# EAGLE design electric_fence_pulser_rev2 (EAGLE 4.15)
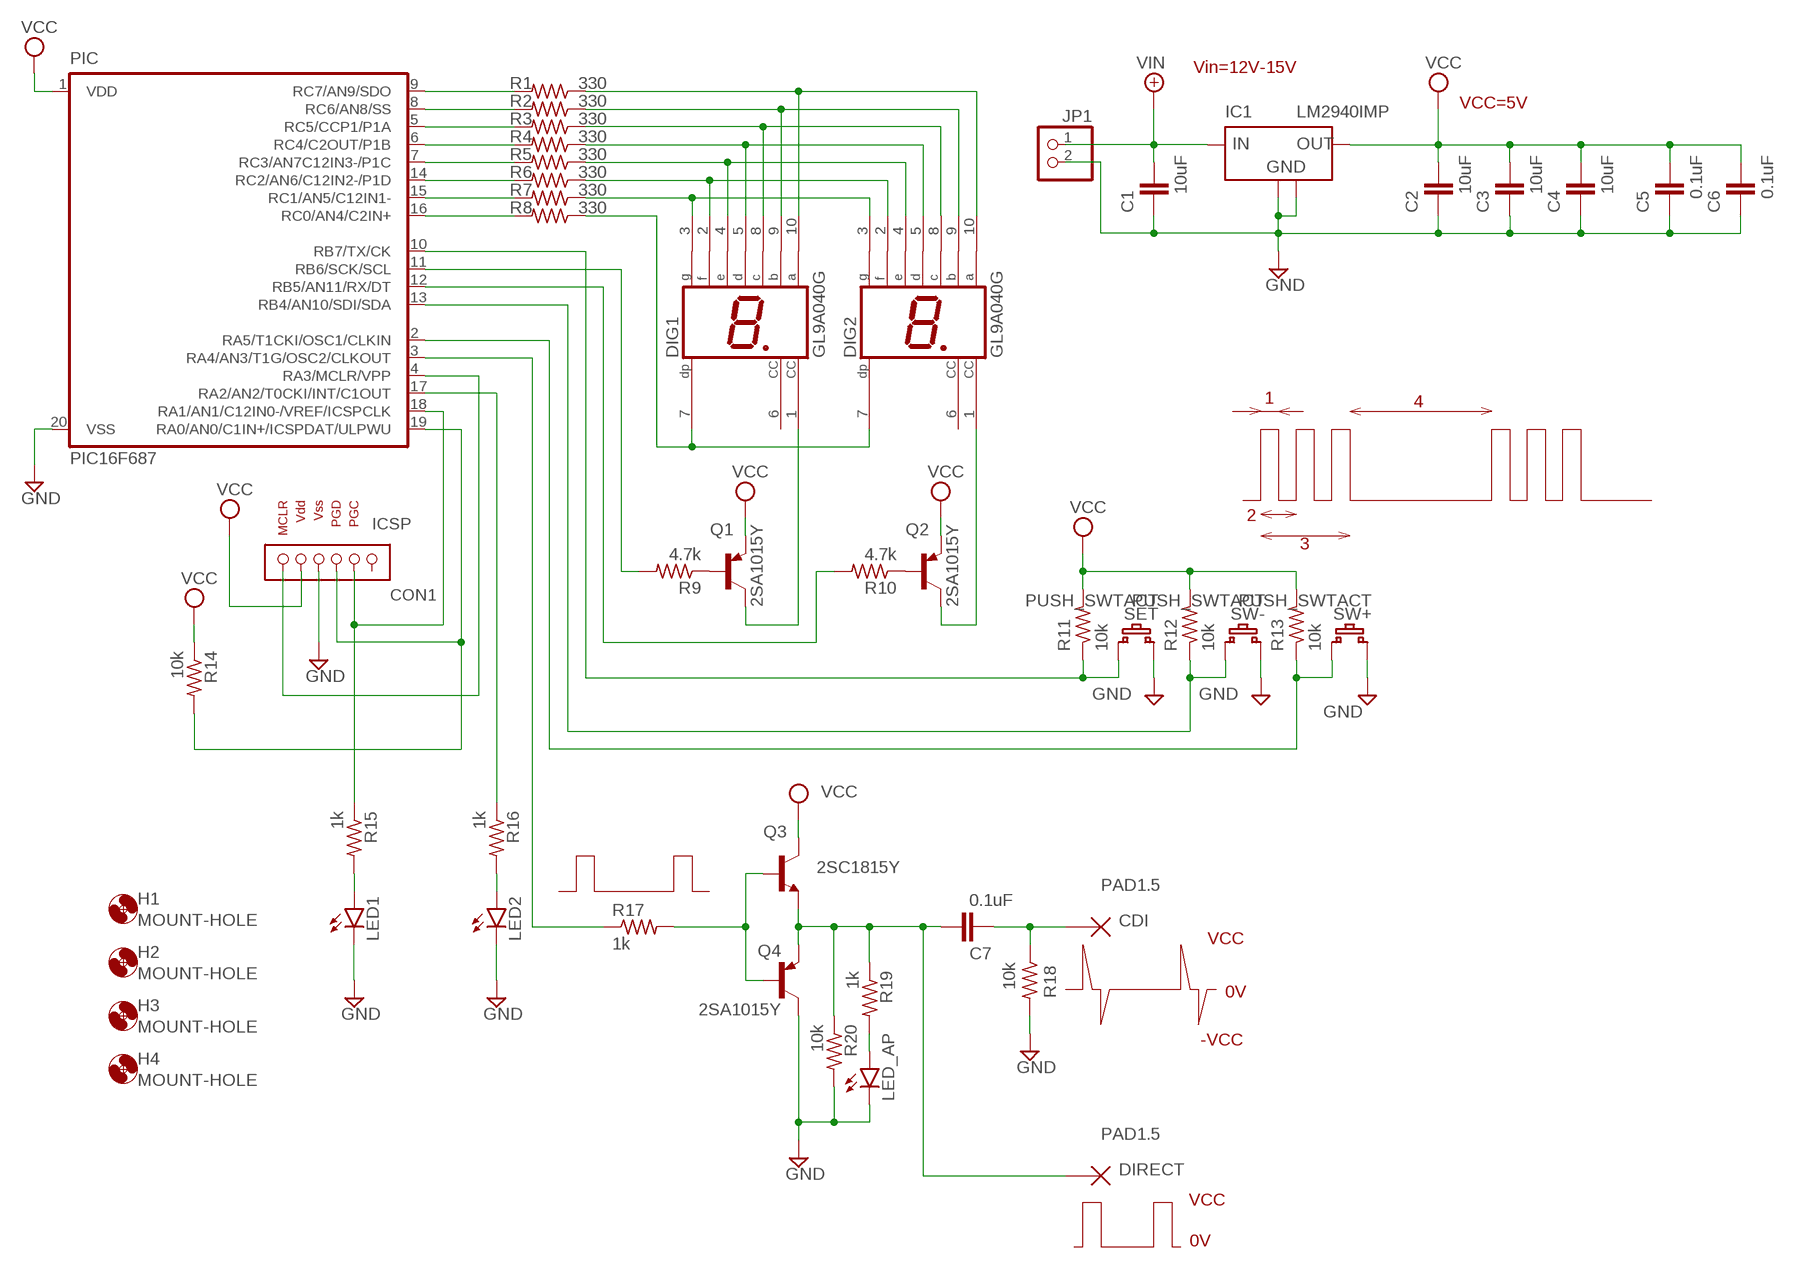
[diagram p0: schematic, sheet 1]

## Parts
C1  10uF  C-EU050-024X044_OLMX  [C050-024X044_OLMX]
C2  10uF  C-EU050-024X044_OLMX  [C050-024X044_OLMX]
C3  10uF  C-EU050-024X044_OLMX  [C050-024X044_OLMX]
C4  10uF  C-EU050-024X044_OLMX  [C050-024X044_OLMX]
C5  0.1uF  C-EU025-024X044_OLMX  [C025-024X044_OLMX]
C6  0.1uF  C-EU025-024X044_OLMX  [C025-024X044_OLMX]
C7  0.1uF  C-EU050-024X044_OLMX  [C050-024X044_OLMX]
CDI  PAD1.5  [PAD_1.5]
CON1  ICSP  PIC_ICSP  [PIC_ICSP]
DIG1  GL9A040G  HD-F103_OLMX  [HDSP-E_OLMX]
DIG2  GL9A040G  HD-F103_OLMX  [HDSP-E_OLMX]
DIRECT  PAD1.5  [PAD_1.5]
H1  MOUNT-HOLE  MOUNT-HOLEONLYRESTRICT  [3.0-HOLL-ONLY-RESTRICT]
H2  MOUNT-HOLE  MOUNT-HOLEONLYRESTRICT  [3.0-HOLL-ONLY-RESTRICT]
H3  MOUNT-HOLE  MOUNT-HOLEONLYRESTRICT  [3.0-HOLL-ONLY-RESTRICT]
H4  MOUNT-HOLE  MOUNT-HOLEONLYRESTRICT  [3.0-HOLL-ONLY-RESTRICT]
IC1  LM2940IMP  LM2940  [SOT223_OLMX]
JP1  PINHD-1X2_OLMX  [1X02_OLMX]
LED1  LED3MM_OLMX  [LED3MM_OLMX]
LED2  LED3MM_OLMX  [LED3MM_OLMX]
LED_AP  LED3MM_OLMX  [LED3MM_OLMX]
PIC  PIC16F687  PIC16F690IP_OLMX  [DIL20_OLMX]
Q1  2SA1015Y  BC636N  [TO-92-BCE?NALLOW]
Q2  2SA1015Y  BC636N  [TO-92-BCE?NALLOW]
Q3  2SC1815Y  BC635-NPN-NALLOW  [TO92-BCE_OLMX_NALLOW]
Q4  2SA1015Y  BC636N  [TO-92-BCE?NALLOW]
R1  330  R-US_0204/5_OLMX  [0204/5_OLMX]
R2  330  R-US_0204/5_OLMX  [0204/5_OLMX]
R3  330  R-US_0204/5_OLMX  [0204/5_OLMX]
R4  330  R-US_0204/5_OLMX  [0204/5_OLMX]
R5  330  R-US_0204/5_OLMX  [0204/5_OLMX]
R6  330  R-US_0204/5_OLMX  [0204/5_OLMX]
R7  330  R-US_0204/5_OLMX  [0204/5_OLMX]
R8  330  R-US_0204/5_OLMX  [0204/5_OLMX]
R9  4.7k  R-US_0204/5_OLMX  [0204/5_OLMX]
R10  4.7k  R-US_0204/5_OLMX  [0204/5_OLMX]
R11  10k  R-US_0204/5_OLMX  [0204/5_OLMX]
R12  10k  R-US_0204/5_OLMX  [0204/5_OLMX]
R13  10k  R-US_0204/5_OLMX  [0204/5_OLMX]
R14  10k  R-US_0204/5_OLMX  [0204/5_OLMX]
R15  1k  R-US_0204/5_OLMX  [0204/5_OLMX]
R16  1k  R-US_0204/5_OLMX  [0204/5_OLMX]
R17  1k  R-US_0204/5_OLMX  [0204/5_OLMX]
R18  10k  R-US_0204/5_OLMX  [0204/5_OLMX]
R19  1k  R-US_0204/5_OLMX  [0204/5_OLMX]
R20  10k  R-US_0204/5_OLMX  [0204/5_OLMX]
SET  PUSH_SWTACT  [TACT_SW]
SW+  PUSH_SWTACT  [TACT_SW]
SW-  PUSH_SWTACT  [TACT_SW]

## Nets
+12V [POWER]: C1.2 IC1.1(IN) JP1.1 ; supply symbol labelled VIN
GND [POWER]: C1.1 C2.1 C3.1 C4.1 C5.1 C6.1 CON1.VSS IC1.2(GND) IC1.4(GND) JP1.2 LED1.K(C) LED2.K(C) LED_AP.K(C) PIC.20(VSS) Q4.C R18.2 R20.2 SET.P$1_1 SW+.P$1_1 SW-.P$1_1
N$1: DIG1.7(DP) DIG2.7(DP) R8.1
N$2: PIC.9(RC7/AN9/SDO) R1.2
N$3: PIC.12(RB5/AN11/RX/DT) R10.2
N$4: PIC.15(RC1/AN5/C12IN1-) R7.2
N$5: PIC.14(RC2/AN6/C12IN2-/P1D) R6.2
N$6: PIC.7(RC3/AN7C12IN3-/P1C) R5.2
N$7: PIC.6(RC4/C2OUT/P1B) R4.2
N$8: PIC.5(RC5/CCP1/P1A) R3.2
N$9: PIC.13(RB4/AN10/SDI/SDA) R12.1 SW-.P$1_2
N$10: PIC.10(RB7/TX/CK) R11.1 SET.P$1_2
N$11: C7.1 CDI.P$1 R18.1
N$12: PIC.8(RC6/AN8/SS) R2.2
N$13: LED_AP.A R19.2
N$14: CON1.MCLR PIC.4(RA3/MCLR/VPP)
N$15: DIG1.1(CC) Q1.C
N$16: DIG2.1(CC) Q2.C
N$18: PIC.11(RB6/SCK/SCL) R9.2
N$19: LED1.A R15.2
N$20: LED2.A R16.2
N$22: Q1.B R9.1
N$23: Q2.B R10.1
N$24: PIC.17(RA2/AN2/T0CKI/INT/C1OUT) R16.1
N$25: Q3.B Q4.B R17.2
N$26: CON1.PGC PIC.18(RA1/AN1/C12IN0-/VREF/ICSPCLK) R15.1
N$27: PIC.2(RA5/T1CKI/OSC1/CLKIN) R13.1 SW+.P$1_2
N$28: PIC.3(RA4/AN3/T1G/OSC2/CLKOUT) R17.1
N$29: C7.2 DIRECT.P$1 Q3.E Q4.E R19.1 R20.1
N$31: DIG1.10(A) DIG2.10(A) R1.1
N$32: CON1.PGD PIC.19(RA0/AN0/C1IN+/ICSPDAT/ULPWU) R14.2
N$35: PIC.16(RC0/AN4/C2IN+) R8.2
N$42: DIG1.9(B) DIG2.9(B) R2.1
N$44: DIG1.5(D) DIG2.5(D) R4.1
N$45: DIG1.2(F) DIG2.2(F) R6.1
N$46: DIG1.4(E) DIG2.4(E) R5.1
N$47: DIG1.3(G) DIG2.3(G) R7.1
N$55: DIG1.8(C) DIG2.8(C) R3.1
VCC [POWER]: C2.2 C3.2 C4.2 C5.2 C6.2 CON1.VDD IC1.3(OUT) PIC.1(VDD) Q1.E Q2.E Q3.C R11.2 R12.2 R13.2 R14.1
Unconnected: CON1.NC DIG1.6(CC) DIG2.6(CC)

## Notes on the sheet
- Vin=12V-15V
- VCC=5V
- 1 | 4
- 2
- 3
- VCC
- 0V
- -VCC
- VCC
- 0V

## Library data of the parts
C1-C7 = rcl:C-EU: CAPACITOR, European symbol
CDI DIRECT = 001mylib:PAD
CON1 = 001mylib:PIC_ICSP
DIG1 DIG2 = display-hp:HD-F103: LED DISPLAY 1-character 7 segment, decimal point right
H1-H4 = holes:MOUNT-HOLE: MOUNTING HOLE with drill center marker
IC1 = linear:LM2940
JP1 = pinhead:PINHD-1X2: PIN HEADER
LED1 LED2 LED_AP = led:LED: LED
PIC = microchip-5:PIC16F690*: MICROCONTROLLER PIC16F690 18 I/O One 16-bit timer Two 8-bit timer Two comparators Precision internal oscillator-software selectable 8 MHz - 32 KHz SSP w/ I2C Compatible Address mask option EUSART LIN 2.0 Compatible ECCP+ w/ PWM Steering 12 A/D Channels ULPW Enhanced Low Power Timer 1 Timer 1 Gate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
Q1 Q2 Q4 = transistor-pnp:BC636*: PNP Transistror
Q3 = transistor:*-NPN-: NPN Transistror
R1-R20 = rcl:R-US_: RESISTOR, American symbol
SET SW+ SW- = 001mylib:PUSH_SW

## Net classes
0 default: width 0.305 mm, drill 0.305 mm
1 POWER: width 0.889 mm, drill 0.457 mm

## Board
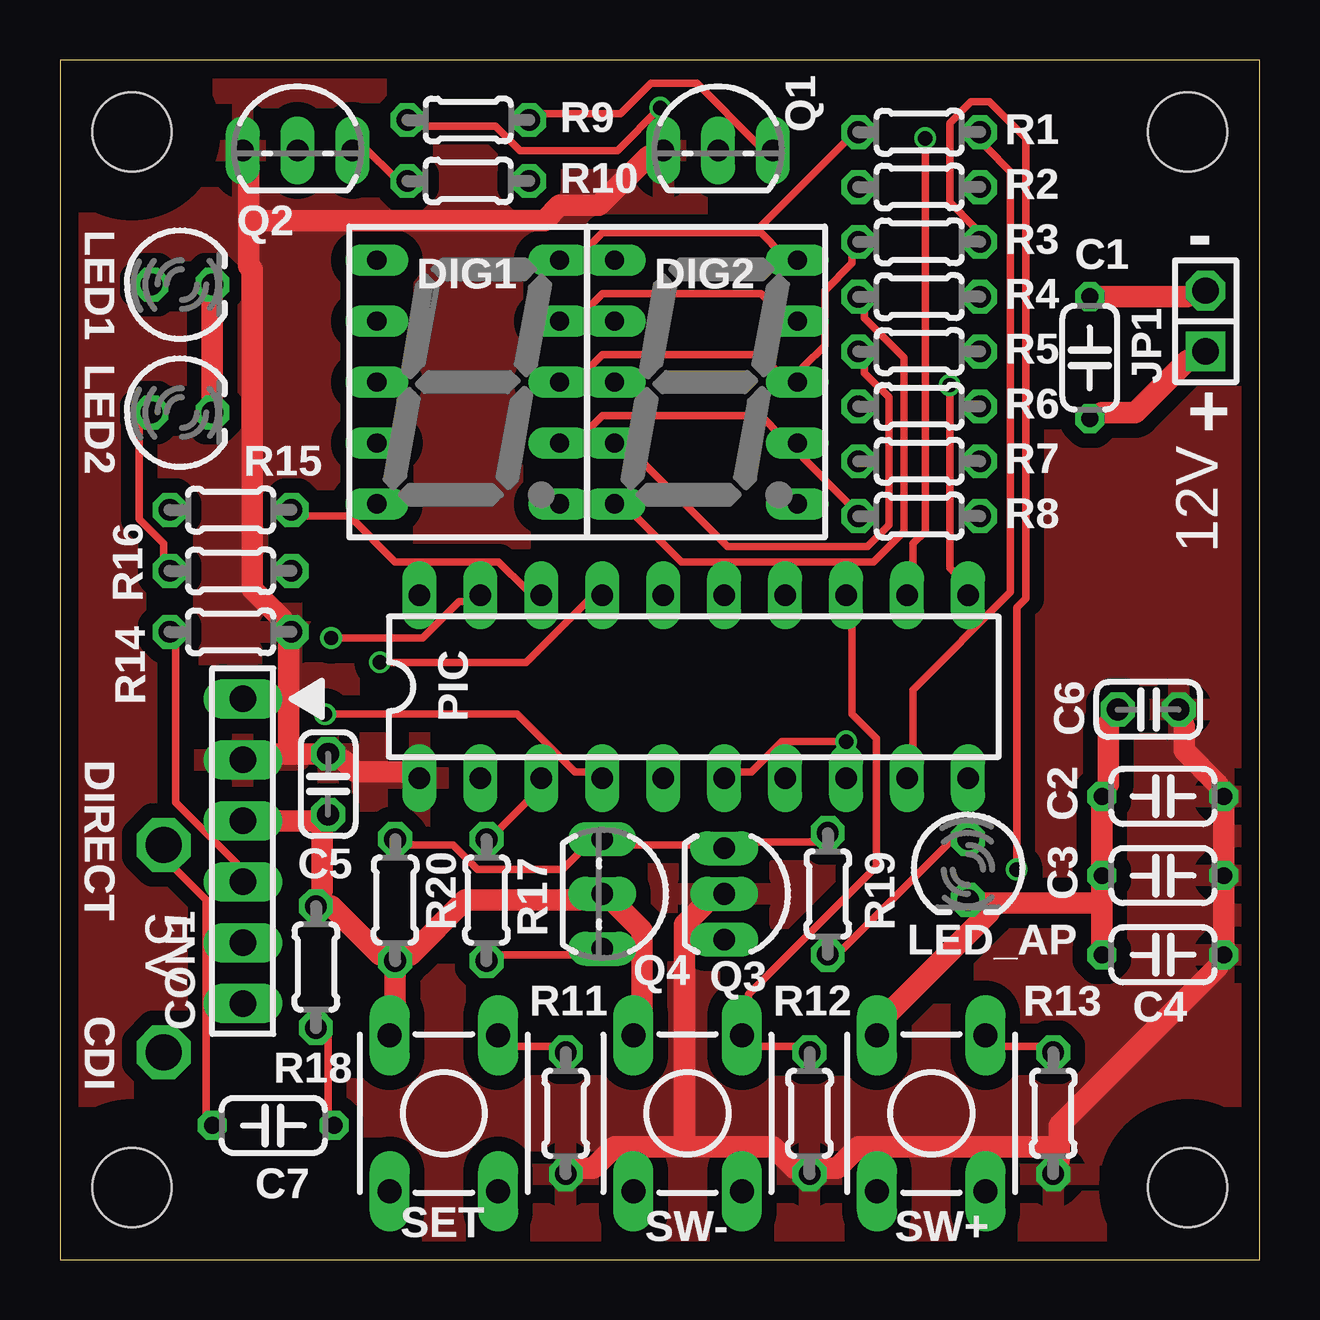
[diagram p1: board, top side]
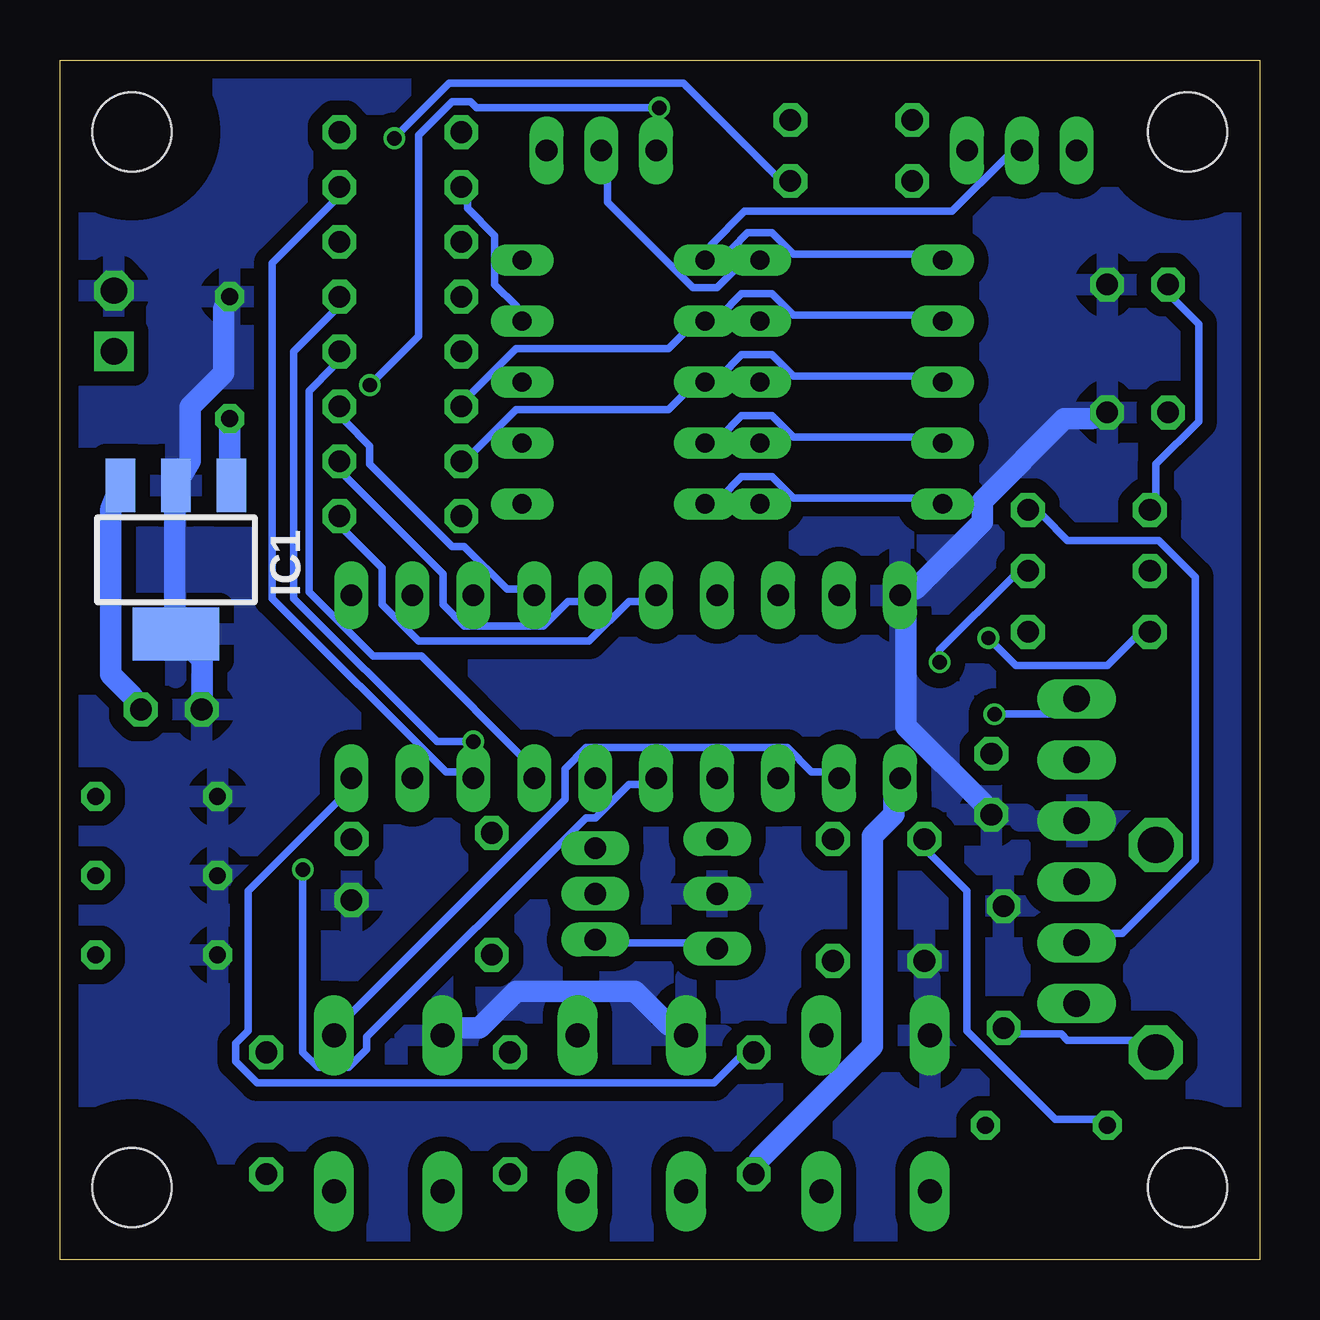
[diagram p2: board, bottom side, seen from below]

Size 50 x 50 mm. Coordinates in mm from the lower left corner, seen from the top.
Outline: 0,0 50,0 50,50 0,50 0,0
Copper layers (1*16): Top 0.035mm / dielectric 1.5mm / Bottom 0.035mm
Design rules "FUSION_IIZUKA_STANDARD": minimum track width 6mil, minimum drill 0.6mm, track to track 8mil, track to pad 8mil, pad to pad 8mil, via to via 8mil, smd to smd 0mil, copper to edge 30mil, drill to drill 10mil, minimum pad ring 10mil, minimum via ring 6mil, stop-mask expansion 2mil, vias tented up to drill 100mil, thermal gap 24mil
vRestrict: 816 lines

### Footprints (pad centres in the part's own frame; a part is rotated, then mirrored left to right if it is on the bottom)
C050-024X044_OLMX = drill 0.7 octagon: 1 -2.54,0; 2 2.54,0
C025-024X044_OLMX = drill 0.9 octagon: 1 -1.27,0; 2 1.27,0
PAD_1.5 = drill 1.5 pad 2.184 octagon: P$1 0,0
PIC_ICSP = drill 1.1 long: MCLR -6.35,0; NC 6.35,0; PGC 3.81,0; PGD 1.27,0; VDD -3.81,0; VSS -1.27,0
HDSP-E_OLMX = drill 0.8 long: 1 -3.81,5.08; 2 -3.81,2.54; 3 -3.81,0; 4 -3.81,-2.54; 5 -3.81,-5.08; 6 3.81,-5.08; 7 3.81,-2.54; 8 3.81,0; 9 3.81,2.54; 10 3.81,5.08
3.0-HOLL-ONLY-RESTRICT = hole 3.3: 0,0
SOT223_OLMX = smd 1.219 x 2.235: 1 -2.311,-3.099; 2 0,-3.099; 3 2.311,-3.099 | smd 3.6 x 2.2: 4 0,3.099
1X02_OLMX = drill 1.1 square: 1 -1.27,0 | drill 1.1 octagon: 2 1.27,0
LED3MM_OLMX = drill 0.9 octagon: A -1.27,0; K 1.27,0
DIL20_OLMX = drill 0.9 long: 1 -11.43,-3.81; 2 -8.89,-3.81; 3 -6.35,-3.81; 4 -3.81,-3.81; 5 -1.27,-3.81; 6 1.27,-3.81; 7 3.81,-3.81; 8 6.35,-3.81; 9 8.89,-3.81; 10 11.43,-3.81; 11 11.43,3.81; 12 8.89,3.81; 13 6.35,3.81; 14 3.81,3.81; 15 1.27,3.81; 16 -1.27,3.81; 17 -3.81,3.81; 18 -6.35,3.81; 19 -8.89,3.81; 20 -11.43,3.81
TO-92-BCE?NALLOW = drill 0.9 long: B 2.286,0; C 0,0; E -2.286,0
TO92-BCE_OLMX_NALLOW = drill 0.9 long: B 1.905,0; C 0,0; E -1.905,0
0204/5_OLMX = drill 0.9 octagon: 1 -2.54,0; 2 2.54,0
TACT_SW = drill 1 pad 1.676 long: P$1_1 -2.261,3.251; P$1_2 2.261,3.251; P$2_1 -2.261,-3.251; P$2_2 2.261,-3.251

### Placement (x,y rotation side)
C1  42.93,37.59 270 top
C2  45.97,19.3 0 top
C3  45.97,16 0 top
C4  45.97,12.7 0 top
C5  11.18,19.81 90 top
C6  45.36,22.93 0 top
C7  8.89,5.59 180 top
CDI  4.32,8.64 270 top
CON1  7.62,17.02 270 top
DIG1  17.02,36.58 0 top
DIG2  26.92,36.58 0 top
DIRECT  4.32,17.27 270 top
H1  47,47 0 top
H2  47,3 0 top
H3  3,3 0 top
H4  3,47 0 top
IC1  45.17,29.17 180 bottom
JP1  47.75,39.12 90 top
LED1  5.08,40.64 0 top
LED2  5.08,35.31 0 top
LED_AP  37.85,16.26 270 top
PIC  26.42,23.88 0 top
Q1  27.43,46.23 0 top
Q2  9.91,46.23 0 top
Q3  27.69,15.24 270 top
Q4  22.61,15.24 270 top
R1  35.81,46.99 0 top
R2  35.81,44.7 0 top
R3  35.81,42.42 0 top
R4  35.81,40.13 0 top
R5  35.81,37.85 0 top
R6  35.81,35.56 0 top
R7  35.81,33.27 0 top
R8  35.81,30.99 0 top
R9  17.02,47.5 180 top
R10  17.02,44.96 0 top
R11  21.08,6.1 270 top
R12  31.24,6.1 270 top
R13  41.4,6.1 270 top
R14  7.11,26.16 180 top
R15  7.11,31.24 180 top
R16  7.11,28.7 180 top
R17  17.78,14.99 270 top
R18  10.67,12.19 90 top
R19  32,15.24 270 top
R20  13.97,14.99 270 top
SET  16,6.1 0 top
SW+  36.32,6.1 0 top
SW-  26.16,6.1 0 top

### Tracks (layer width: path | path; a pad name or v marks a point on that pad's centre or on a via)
+12V
  Top 0.889: C1.2 43.43,35.31 44.83,35.31 46.99,37.47 JP1.1
  Bottom 0.889: IC1.1 42.93,33.27 C1.2
GND
  Top 0.889: 43.43,14.86 C4.1 | 43.43,14.86 C3.1 C2.1 43.69,19.81 43.69,22.35 C6.1 | 38.73,14.86 38.48,14.86 LED_AP.K | 38.73,14.86 43.43,14.86 | SW+.P$1_1 34.42,10.16 38.73,14.48 38.73,14.86 | C1.1 46.99,40.13 JP1.2 | SW-.P$1_1 24.26,10.16 24.26,13.72 23.11,14.86 Q4.C 21.97,14.99 16.89,14.99 14.61,12.7 R20.2 | LED2.K LED1.K | R20.2 13.97,10.16 SET.P$1_1 | CON1.VSS 10.54,18.29 C5.1 10.92,17.91 10.92,15.37 R18.2 11.3,14.73 13.34,12.7 R20.2
  Bottom 0.889: C6.1 44.07,23.62 44.07,25.02 IC1.4 45.21,27.05 45.21,31.24 IC1.2 44.58,33.27 44.58,35.56 43.18,36.96 43.18,39.62 C1.1 | C5.1 11.56,19.05 14.73,22.23 14.73,27.05 PIC.20 14.35,27.94 11.56,30.73 11.56,31.62 8.13,35.05 6.99,35.05 LED2.K | SW+.P$1_1 33.27,9.65 32.51,9.65 30.99,11.18 26.04,11.18 24.64,9.78 SW-.P$1_1
  pour Bottom (isolate 0.61): 0,50 50,50 50,0 0,0
N$1
  Top 0.305: DIG1.7 21.46,34.29 21.72,34.29 22.61,35.18 29.21,35.18 30.1,34.29 DIG2.7 30.99,33.4 32.89,31.5 R8.1
N$2
  Top 0.305: PIC.9 35.56,20.7 35.56,23.75 39.62,27.81 39.62,45.34 38.61,46.35 R1.2
N$3  (via drill 0.6)
  Top 0.305: v36.07,46.74 36.07,30.35 35.56,29.84 35.56,28.32 PIC.12
  Bottom 0.305: v36.07,46.74 33.78,49.02 24,49.02 20.19,45.21 R10.2
N$4
  Bottom 0.305: PIC.15 28.32,27.43 28.83,27.43 29.84,26.42 33.15,26.42 34.04,27.3 34.04,28.57 38.1,32.64 R7.2
N$5
  Bottom 0.305: PIC.14 30.86,27.94 31.37,27.94 33.15,29.72 33.66,29.72 37.08,33.15 37.08,33.91 38.1,34.92 R6.2
N$6
  Bottom 0.305: PIC.7 30.48,20.7 34.92,25.15 36.96,25.15 39.62,27.81 39.62,36.2 38.61,37.21 R5.2
N$7  (via drill 0.6)
  Top 0.305: v32.77,21.59 30.1,21.59 28.83,20.32 28.32,20.32 PIC.6
  Bottom 0.305: v32.77,21.59 34.29,21.59 40.26,27.56 40.26,37.85 38.61,39.5 R4.2
N$8  (via drill 0.6)
  Top 0.305: v39.88,16.26 39.88,27.18 40.26,27.56 40.26,46.74 38.73,48.26 37.97,48.26 37.08,47.37 37.08,44.07 38.1,43.05 R3.2
  Bottom 0.305: v39.88,16.26 39.88,8.64 39.24,8 37.97,8 37.21,8.76 37.21,9.27 28.07,18.41 27.69,18.41 26.29,19.81 25.78,19.81 PIC.5
N$9
  Top 0.305: R12.1 30.61,8.89 29.08,8.89 SW-.P$1_2 28.7,10.16 28.7,11.05 34.04,16.38 34.04,21.72 33.02,22.73 33.02,27.05 PIC.13
N$10
  Top 0.305: R11.1 20.45,8.89 18.92,8.89 SET.P$1_2
  Bottom 0.305: PIC.10 38.1,19.43 42.16,15.37 42.16,9.53 42.67,9.02 42.67,8.26 41.78,7.37 22.73,7.37 21.72,8.38 R11.1
N$11
  Top 0.305: C7.1 11.18,6.1 11.18,9.27 R18.1
  Bottom 0.305: R18.1 10.03,9.4 8.26,9.4 8,9.14 5.33,9.14 CDI.P$1
N$12
  Bottom 0.305: PIC.8 33.4,20.32 33.91,20.32 41.15,27.56 41.15,41.53 38.61,44.07 R2.2
N$13
  Top 0.305: R19.2 32.64,12.95 37.21,17.53 LED_AP.A
N$14  (via drill 0.6)
  Top 0.305: v11.05,22.73 19.05,22.73 21.46,20.32 21.97,20.32 PIC.4
  Bottom 0.305: v11.05,22.73 8.13,22.73 CON1.MCLR
N$15
  Bottom 0.305: DIG1.1 13.84,41.91 19.43,41.91 20.32,42.8 21.34,42.8 21.97,42.16 21.97,41.15 22.61,40.51 23.62,40.51 27.18,44.07 27.18,45.59 Q1.C
N$16
  Bottom 0.305: DIG2.1 22.86,42.29 21.46,43.69 12.83,43.69 10.54,45.97 Q2.C
N$18  (via drill 0.6)
  Top 0.305: v25.02,48.01 23.24,46.23 19.18,46.23 18.16,47.24 15.11,47.24 R9.2 | v37.08,36.45 37.08,28.83 37.59,28.32 PIC.11
  Bottom 0.305: v25.02,48.01 32.64,48.01 32.89,48.26 33.66,48.26 35.05,46.86 35.05,38.48 v37.08,36.45
N$19
  Bottom 0.305: R15.2 4.32,31.88 4.32,33.15 2.54,34.92 2.54,38.99 3.56,40.01 LED1.A
N$20
  Top 0.305: R16.2 4.32,29.34 4.32,29.84 3.3,30.86 3.3,34.92 LED2.A
N$22
  Top 0.305: R9.1 20.19,47.75 23.37,47.75 24.64,49.02 26.54,49.02 29.08,46.48 Q1.B
N$23
  Top 0.305: R10.1 13.84,45.21 12.83,46.23 Q2.B
N$24  (via drill 0.6)
  Top 0.305: v13.34,24.89 19.43,24.89 21.97,27.43 PIC.17
  Bottom 0.305: v13.34,24.89 13.34,25.4 10.29,28.45 R16.1
N$25
  Top 0.305: R17.2 18.41,12.7 21.97,12.7 Q4.B
  Bottom 0.305: Q3.B 27.05,13.21 23.24,13.21 Q4.B
N$26
  Top 0.305: R15.1 10.29,30.99 12.06,30.99 13.97,29.08 18.29,29.08 19.43,27.94 PIC.18
  Bottom 0.305: CON1.PGC 6.86,13.59 5.71,13.59 2.67,16.64 2.67,28.45 4.19,29.97 8,29.97 9.02,30.99 R15.1
N$27
  Top 0.305: R13.1 40.77,8.89 39.24,8.89 SW+.P$1_2
  Bottom 0.305: PIC.2 18.16,20.32 18.67,20.32 19.68,21.34 28.07,21.34 28.96,20.45 28.96,19.18 38.1,10.03 SW+.P$1_2
N$28
  Top 0.305: R17.1 18.29,17.91 19.81,19.43 PIC.3
N$29
  Top 0.305: C7.2 6.1,6.1 6.1,14.99 4.83,16.26 DIRECT.P$1 | R19.1 31.5,17.4 28.32,17.4 Q3.E 27.05,17.27 23.24,17.27 Q4.E 21.97,17.27 20.95,16.26 17.4,16.26 16.38,17.27 14.61,17.27 R20.1
  Bottom 0.305: C7.2 6.86,5.84 8.51,5.84 12.19,9.53 12.19,15.37 13.72,16.89 R20.1
N$31
  Top 0.305: 29.08,42.8 29.21,42.8 30.1,41.91 DIG2.10 | 29.08,42.8 22.61,42.8 21.72,41.91 21.46,41.91 DIG1.10 | R1.1 32.77,46.61 29.08,42.93 29.08,42.8
N$32  (via drill 0.6)
  Top 0.305: R14.2 4.83,25.53 4.83,19.05 7.37,16.51 CON1.PGD | v11.3,25.91 15.11,25.91 16.64,27.43 16.89,27.43 PIC.19
  Bottom 0.305: v11.3,25.91 10.16,24.77 6.35,24.77 5.21,25.91 R14.2
N$35
  Bottom 0.305: PIC.16 25.78,27.43 26.29,27.43 27.94,25.78 35.05,25.78 36.58,27.3 36.58,28.83 38.1,30.35 R8.2
N$42
  Top 0.305: DIG1.9 21.46,39.37 21.72,39.37 22.61,40.26 29.21,40.26 30.1,39.37 DIG2.9
  Bottom 0.305: R2.1 33.02,44.07 33.02,43.81 31.88,42.67 31.88,40.64 30.99,39.75 DIG2.9
N$44
  Top 0.305: R4.1 33.53,39.5 33.53,39.24 35.18,37.59 35.18,30.35 33.91,29.08 25.91,29.08 23.75,31.24 DIG2.5
  Bottom 0.305: DIG1.5 13.84,31.75 19.43,31.75 20.32,32.64 21.59,32.64 22.48,31.75 DIG2.5
N$45
  Bottom 0.305: DIG1.2 13.84,39.37 19.43,39.37 20.32,40.26 21.59,40.26 22.48,39.37 DIG2.2 23.75,38.86 24.64,37.97 30.99,37.97 32.89,36.07 R6.1
N$46
  Top 0.305: R5.1 33.53,37.21 33.53,36.96 34.54,35.94 34.54,30.61 33.66,29.72 27.81,29.72 23.75,33.78 DIG2.4
  Bottom 0.305: DIG1.4 13.84,34.29 19.43,34.29 20.32,35.18 21.59,35.18 22.48,34.29 DIG2.4
N$47
  Bottom 0.305: DIG1.3 13.84,36.83 19.43,36.83 20.32,37.72 21.59,37.72 22.48,36.83 DIG2.3 23.75,36.32 24.64,35.43 30.99,35.43 32.77,33.66 R7.1
N$55
  Top 0.305: DIG1.8 21.46,36.83 21.72,36.83 22.61,37.72 29.21,37.72 30.1,36.83 DIG2.8 30.99,37.21 31.88,38.1 31.88,40.39 33.02,41.53 33.02,41.78 R3.1
VCC
  Top 0.889: 9.53,21.08 8.38,21.08 CON1.VDD | 9.53,21.08 C5.2 11.81,20.83 12.32,20.32 14.35,20.32 PIC.1 | 7.87,43.31 7.87,41.4 8,41.27 8,27.94 9.27,26.67 R14.1 9.53,25.53 9.53,21.08 | 7.87,43.31 7.87,45.59 Q2.E | Q1.E 24.51,45.97 22.48,43.94 20.83,43.94 20.19,43.31 7.87,43.31 | 26.04,4.7 29.72,4.7 30.61,3.81 R12.2 31.88,3.81 32.38,3.81 33.27,4.7 41.66,4.7 | 26.04,4.7 23.11,4.7 22.23,3.81 21.72,3.81 R11.2 | Q3.C 27.05,14.99 26.04,13.97 26.04,4.7 | 41.66,4.7 41.66,5.59 48.26,12.19 C4.2 C3.2 C2.2 48.26,19.81 46.86,21.21 46.86,22.23 C6.2 | 41.66,4.7 41.66,4.19 R13.2
  Bottom 0.889: IC1.3 47.88,31.24 47.88,24.38 46.99,23.5 C6.2 | PIC.1 15.24,19.43 15.24,18.54 16.13,17.65 16.13,8.89 20.83,4.19 R11.2
  pour Top (isolate 0.61): 0,50 50,50 50,0 0,0

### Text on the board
tPlace: - | + | 12V | 5V
_tNames: R9 | Q1 | R1 | R10 | R2 | LED1 | Q2 | C1 | R3 | DIG1 | DIG2 | R4 | LED2 | R5 | JP1 | R6 | R15 | R7 | R16 | R8 | R14 | PIC | C6 | DIRECT | C2 | C5 | R20 | R17 | R19 | C3 | LED_AP | Q3 | Q4 | CDI | R11 | R12 | R13 | C4 | R18 | C7 | SET | SW- | SW+
_bNames: IC1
